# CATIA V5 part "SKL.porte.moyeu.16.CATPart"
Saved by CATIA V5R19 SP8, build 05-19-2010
Part number: SKL.porte.moyeu.16
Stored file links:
  G:\EU_thinkMotion\CFAO_2010\MMS_groupe3\MMS_groupe3\jbonnamy\jbonnamy_cfao\SKL.porte.moyeu.16.CATPart
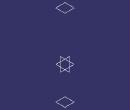
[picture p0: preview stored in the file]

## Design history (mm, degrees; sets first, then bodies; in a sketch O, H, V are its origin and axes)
Body1 (main body)
  Plane1 "Plan.sup.porte.moyeu": type Offset, RefPlane xy-plane, Offset 12
  Plane2 "Plan.inf.porte.moyeu": type Offset, RefPlane xy-plane, Offset 8, reversed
